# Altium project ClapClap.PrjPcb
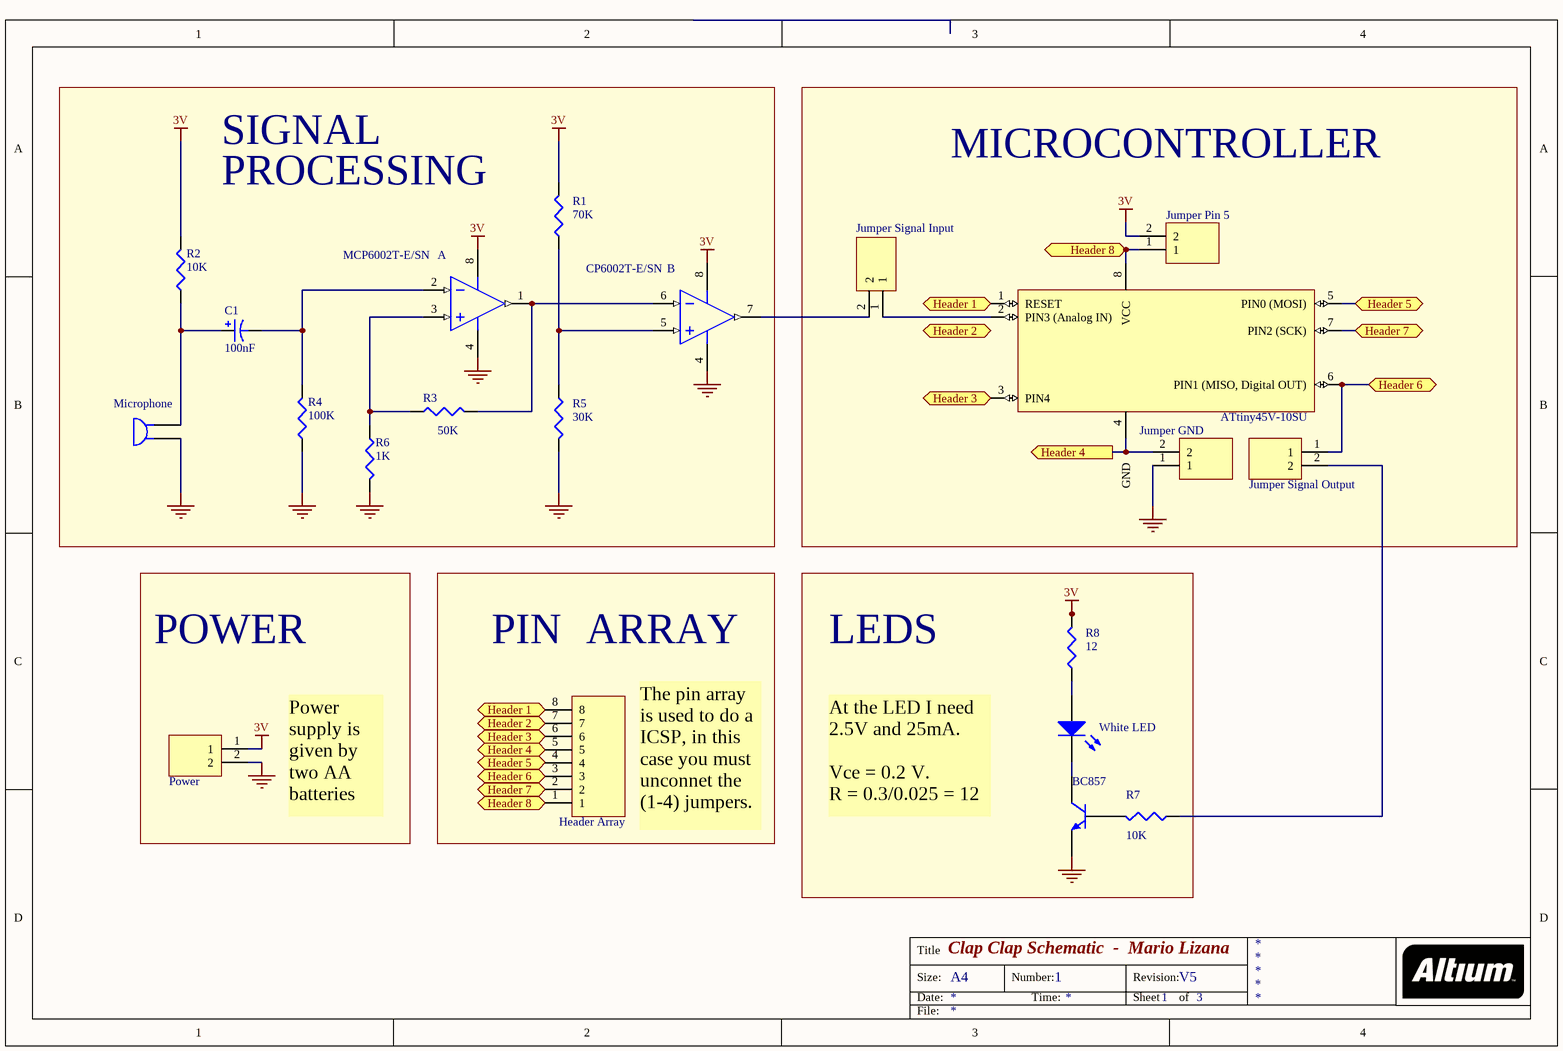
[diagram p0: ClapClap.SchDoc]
1 sheet, 21 parts. Net scope: flat (ports and power ports of the same name join across sheets).
Board file: ClapClapV9.PcbDoc

## Sheet ClapClap.SchDoc: Clap Clap Schematic  -  Mario Lizana
size A4; ApprovedBy: 2; Author: Mario Lizana; DocumentNumber: 1; Revision: V5; SheetNumber: 1; SheetTotal: 3; PageSetup: Record=PageOptions¦CenterHorizontal=True¦CenterVertical=True¦PrintScale=1.00¦XCorrection=1.00¦YCorrection=1.00¦PrintKind=0¦BorderSize=5000000¦LeftOffset=0¦BottomOffset=0¦Orientation=2¦PaperLength=1000¦PaperWidth=1000¦Scale=100¦PaperSource=7¦PrintQuality=600¦MediaType=1¦DitherType=10¦PrintScaleMode=0¦PaperKind=A4¦PaperIndex=9; d: wrg

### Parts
1  Jumper Signal Input  [1x2x2.54 Pin Header TH V]
2  Jumper GND  [1x2x2.54 Pin Header TH V]
3  Jumper Signal Output  [1x2x2.54 Pin Header TH V]
4  Power  [1x2x2.54 Pin Header TH V]
?  MCP6002T-E/SN  [SOIC-SN8_N]  (part A of 2)
C1  value 100nF  [C0805]  (hidden comment: Cap Pol3)
CONN?  Header Array  [1x8x2.54 Pin Header TH V]
D4  White LED  [6-0805_N]
Jumper_Pin_5  Connector  [1x2x2.54 Pin Header TH V]  (value not drawn)
MK1  Microphone  [TO-52]
Q1  BC857  [SOT-23B_N]
R1  value 70K  [J1-0603]  (hidden comment: Res3)
R2  value 10K  [J1-0603]  (hidden comment: Res3)
R3  value 50K  [J1-0603]  (hidden comment: Res3)
R4  value 100K  [J1-0603]  (hidden comment: Res3)
R5  value 30K  [J1-0603]  (hidden comment: Res3)
R6  value 1K  [J1-0603]  (hidden comment: Res3)
R7  value 10K  [J1-0603]  (hidden comment: Res3)
R8  value 12  [J1-0603]  (hidden comment: Res3)
U1  ATtiny45V-10SU  [8S2_N]
  CP6002T-E/SN  [SOIC-SN8_N]  (part B of 2)

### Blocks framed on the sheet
MICROCONTROLLER: 1-3 Jumper_Pin_5 U1
POWER: 4
LEDS: D4 Q1 R7 R8

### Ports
Header 1, Header 1 (bidir), Header 2, Header 2 (bidir), Header 3, Header 3 (bidir), Header 4, Header 4 (out), Header 5, Header 5 (bidir), Header 6, Header 6 (bidir), Header 7, Header 7 (bidir), Header 8

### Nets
3V: 4.1 ?.8(VDD) Jumper_Pin_5.2 R1.2 R2.2 R8.2 .8(VDD)
GND: 2.1 4.2 ?.4(VSS) MK1.2 Q1.3(E) R4.1 R5.2 R6.2 .4(VSS)
Net1_1: 1.1 U1.2(PIN3_(Analog_IN))
Net1_2: 1.2 .7(VOUTB)
Net2_2: 2.2 CONN?.5 ; port Header 4
Net3_1: 3.1 CONN?.3 U1.6(PIN1_(MISO,_Digital_OUT)) ; port Header 6
Net3_2: 3.2 R7.1
Net?_1: ?.1(VOUTA) R3.2 .6(VINB-)
Net?_2: ?.2(VINA-) C1.2 R4.2
Net?_3: ?.3(VINA+) R3.1 R6.1
NetC1_1: C1.1 MK1.1 R2.1
NetCONN?_1: CONN?.1 Jumper_Pin_5.1 U1.8(VCC) ; port Header 8
NetCONN?_2: CONN?.2 U1.7(PIN2_(SCK)) ; port Header 7
NetCONN?_6: CONN?.6 U1.3(PIN4) ; port Header 3
NetCONN?_7: CONN?.7 ; port Header 2
NetCONN?_8: CONN?.8 U1.1(RESET) ; port Header 1
NetD4_1: D4.1(A) R8.1
NetD4_2: D4.2(K) Q1.1(C)
NetQ1_2: Q1.2(B) R7.2
NetR1_1: R1.1 R5.1 .5(VINB+)
NetU1_5: U1.5(PIN0_(MOSI)) ; port Header 5

Not connected (* = marked no-connect by the designer): CONN? 4; U1 4(GND)

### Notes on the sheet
- PROCESSING
- SIGNAL
- PIN
- ARRAY
- Power supply is given by two AA batteries
- The pin array is used to do a ICSP, in this case you must unconnet the (1-4) jumpers.
- At the LED I need 2.5V and 25mA.
  Vce = 0.2 V.
  R = 0.3/0.025 = 12

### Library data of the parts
1-4 Jumper_Pin_5 = Header 1x2
?  = MCP6002T-E/SN: 1 MHz, Low-Power Operational Amplifier, 8-Pin SOIC, Extended Temperature, Tape and Reel
C1 = Cap Pol3: Polarized Capacitor (Surface Mount)
CONN? = Header 1x8
D4 = LED3: Typical BLUE SiC LED
MK1 = Mic1
Q1 = QNPN: NPN Bipolar Transistor
R1-R8 = Res3: Resistor
U1 = ATtiny45V-10SU: Low Power tinyAVR® 8-Bit Microcontroller, 4K Flash Memory, 10MHz, Industrial Temperature, 8-Lead SOIC, Pb-Free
